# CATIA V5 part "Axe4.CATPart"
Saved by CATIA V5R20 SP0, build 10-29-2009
Part number: Axe4
Bounding box of the stored display mesh (mm): x 30.5 to 37.5, y 27 to 34, z -18 to -3.5
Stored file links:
  E:\Boulot\SeaTech\2eme ANNEE\FabricationAdditive\TP_MOSM_CREM\Projet Sauterelle de serrage\CAO Assemblage Sauterelle\Axe4.CATPart
  E:\Boulot\SeaTech\2eme ANNEE\FabricationAdditive\TP_MOSM_CREM\Projet Sauterelle de serrage\CAO Assemblage Sauterelle\Sauterelle_horizontale_05120-06.CATPart
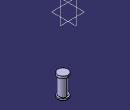
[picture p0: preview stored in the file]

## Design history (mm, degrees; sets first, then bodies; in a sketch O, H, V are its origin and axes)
Body1 (main body)
  Solid1 "05120-06_12": solid without history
